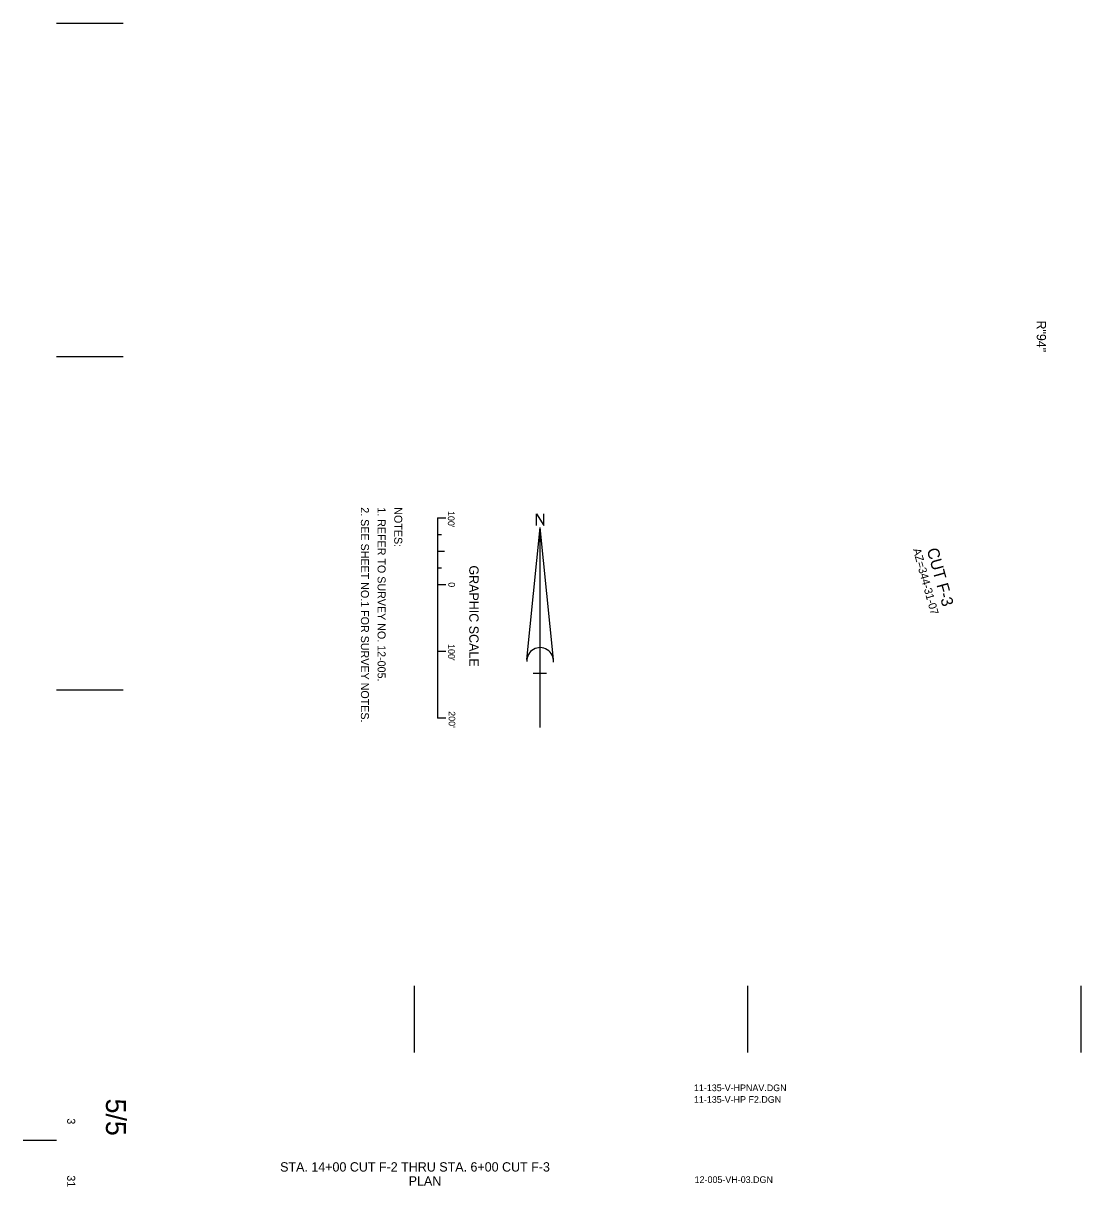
# Model space of a CAD drawing. Extents: x 585414 to 588664, y 1932755 to 1936856.
# Drawn here: x 585414 to 587000, y 1932755 to 1934500 of the extents above; entities that cross this region are included whole.
import ezdxf

# ---------------------------------------------------------------- set-up
doc = ezdxf.new("R2010")
doc.units = 0
for name, color, linetype in [('V-ANNO-KEYN', 7, 'Continuous'), ('V-ANNO-NOTE', 7, 'Continuous'), ('V-ANNO-NPLT', 7, 'Continuous'), ('V-ANNO-PATT', 7, 'Continuous'), ('V-ANNO-RDME', 7, 'Continuous'), ('V-ANNO-SYMB', 7, 'Continuous'), ('V-DUCT-MULT-IDEN', 7, 'Continuous')]:
    doc.layers.add(name, color=color, linetype=linetype)

msp = doc.modelspace()

# ---------------------------------------------------------------- linework, layer by layer
at = {"layer": 'V-ANNO-KEYN'}
for p, q in [((585463.7, 1934500), (585563.7, 1934500)), ((585463.7, 1934000), (585563.7, 1934000)), ((585463.7, 1933500), (585563.7, 1933500)), ((586000, 1933056), (586000, 1932956)), ((586500, 1933056), (586500, 1932956)), ((587000, 1933056), (587000, 1932956))]:
    msp.add_line(p, q, dxfattribs=at)
at = {"layer": 'V-ANNO-NOTE'}
for p, q in [((586035.3, 1933758), (586035.3, 1933457.9)), ((586035.3, 1933758), (586047.8, 1933758)), ((586169.1, 1933545.5), (586189, 1933743.5)), ((586189, 1933443.5), (586189, 1933743.5)), ((586208.9, 1933545.5), (586189, 1933743.5)), ((586035.6, 1933733), (586041.3, 1933733)), ((586035.3, 1933708), (586045.5, 1933708)), ((586035.6, 1933708), (586041.3, 1933708)), ((586035.6, 1933683), (586041.3, 1933683)), ((586035.3, 1933658), (586047.8, 1933658)), ((586035.3, 1933658), (586041.3, 1933658)), ((586035.3, 1933658), (586047.8, 1933658)), ((586035.3, 1933558), (586047.8, 1933558)), ((586198.5, 1933524.5), (586178.5, 1933524.5)), ((586035.3, 1933458), (586047.8, 1933458))]:
    msp.add_line(p, q, dxfattribs=at)
msp.add_lwpolyline([(586183.5, 1933746.7), (586183.5, 1933764.2), (586194.4, 1933746.7), (586194.4, 1933764.2)], dxfattribs=at)
msp.add_arc((586189, 1933543.5), 20, 355.2984, 182.0673, dxfattribs=at)
at = {"layer": 'V-ANNO-RDME'}
msp.add_line((585413.7, 1932824.8), (585463.7, 1932824.8), dxfattribs=at)

# ---------------------------------------------------------------- texts
at = {"layer": 'V-ANNO-NOTE'}
for s, height, p in [("100'", 10, (586050.6, 1933768.4)), ('GRAPHIC SCALE', 14, (586082.7, 1933686.8)), ('0', 10, (586051.4, 1933661.5)), ("100'", 10, (586051, 1933568.8)), ("200'", 10, (586051.7, 1933468.1))]:
    msp.add_text(s, height=height, rotation=270, dxfattribs=at).set_placement(p)
at = {"layer": 'V-ANNO-NPLT'}
for s, p in [('2. SEE SHEET NO.1 FOR SURVEY NOTES.', (585920.2, 1933774)), ('1. REFER TO SURVEY NO. 12-005.', (585945.2, 1933774)), ('NOTES:', (585970.2, 1933774))]:
    msp.add_text(s, height=12, rotation=270, dxfattribs=at).set_placement(p)
at = {"layer": 'V-ANNO-PATT'}
for s, height, rotation, p in [('11-135-V-HPNAV.DGN                  ', 10, 360, (586419.8, 1932898.2)), ('11-135-V-HP F2.DGN                  ', 10, 360, (586419.8, 1932880.7)), (' 5/5  ', 30, 270, (585537.8, 1932898.2)), (' 3  ', 12, 270, (585479.6, 1932861.9)), ('       STA. 14+00 CUT F-2 THRU STA. 6+00 CUT F-3       ', 14, 360, (585762.6, 1932777.6)), (' 31 ', 12, 270, (585479.6, 1932776.4)), ('                          PLAN                         ', 14, 360, (585856.6, 1932756.6)), ('12-005-VH-03.DGN                    ', 10, 360, (586420.8, 1932760.5))]:
    msp.add_text(s, height=height, rotation=rotation, dxfattribs=at).set_placement(p)
at = {"layer": 'V-ANNO-SYMB'}
msp.add_text('R"94"', height=13.92, rotation=270, dxfattribs=at).set_placement((586934, 1934054.1))
at = {"layer": 'V-DUCT-MULT-IDEN'}
for s, height, p in [('AZ=344-31-07', 12, (586748.1, 1933710.8)), ('CUT F-3', 17.52, (586768.9, 1933710.4))]:
    msp.add_text(s, height=height, rotation=285.4813, dxfattribs=at).set_placement(p)

doc.saveas('drawing.dxf')
